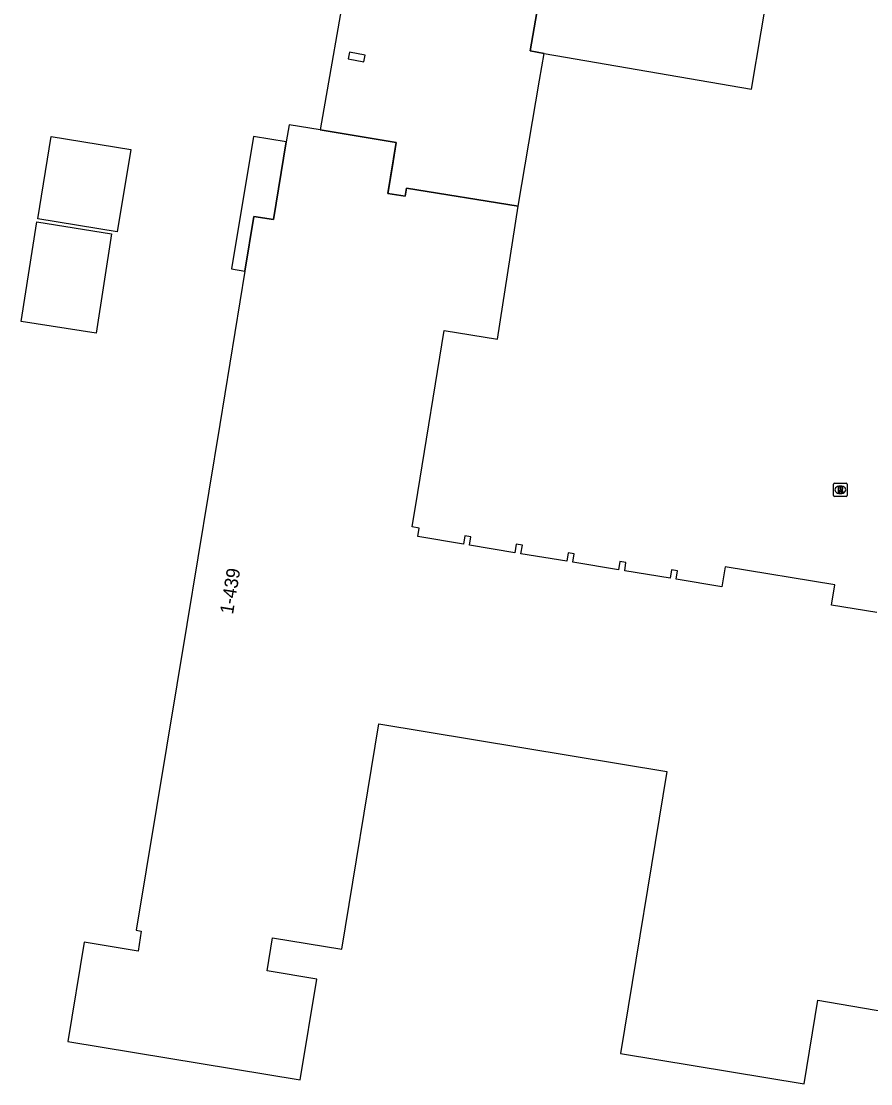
# Model space of a CAD drawing. Extents: x 161258 to 161838, y 380836 to 381727.
# Drawn here: x 161593.1 to 161656.3, y 380892.6 to 380971.7 of the extents above; entities that cross this region are included whole.
import ezdxf

# ---------------------------------------------------------------- set-up
doc = ezdxf.new("R2010")
doc.units = 0
for name, color, linetype in [('IMGEO_Pand', 7, 'Continuous'), ('IMGEO_Pand_nummerreeks', 7, 'Continuous'), ('IMGEO_Pand_overbouw', 7, 'Continuous'), ('IMGEO_Rioolput', 7, 'Continuous')]:
    doc.layers.add(name, color=color, linetype=linetype)

msp = doc.modelspace()

# ---------------------------------------------------------------- linework, layer by layer
at = {"layer": 'IMGEO_Pand'}
for points in [[(161632.262, 380976.901), (161630.974, 380969.465), (161632.027, 380969.284), (161647.439, 380966.629), (161648.17, 380970.892), (161648.549, 380973.103), (161651.15, 380972.652), (161651.976, 380977.422), (161651.777, 380977.456), (161649.385, 380977.871), (161654.985, 381010.445), (161638.525, 381013.267), (161638.42, 381012.654), (161638.251, 381011.67), (161631.061, 381012.91), (161630.098, 381007.334), (161629.73, 381005.204), (161629.086, 381001.476), (161636.289, 381000.232), (161632.862, 380980.375)], [(161618.593, 380968.659), (161618.689, 380969.154), (161617.523, 380969.382), (161617.426, 380968.888), (161618.593, 380968.659)], [(161656.763, 380927.677), (161653.392, 380928.226), (161653.642, 380929.725), (161645.499, 380931.083), (161645.249, 380929.584), (161641.842, 380930.147), (161641.949, 380930.781), (161641.499, 380930.857), (161641.392, 380930.221), (161638.012, 380930.779), (161638.107, 380931.409), (161637.65, 380931.478), (161637.556, 380930.855), (161634.158, 380931.416), (161634.257, 380932.051), (161633.801, 380932.122), (161633.703, 380931.491), (161630.295, 380932.054), (161630.398, 380932.688), (161629.943, 380932.762), (161629.84, 380932.129), (161626.462, 380932.687), (161626.562, 380933.32), (161626.107, 380933.392), (161626.007, 380932.763), (161622.613, 380933.323), (161622.717, 380933.965), (161622.19, 380934.05), (161622.609, 380936.618), (161624.576, 380948.664), (161628.543, 380948.011), (161630.074, 380957.903), (161621.778, 380959.252), (161621.681, 380958.659), (161620.398, 380958.868), (161621.003, 380962.649), (161615.362, 380963.591), (161613.042, 380963.978), (161612.832, 380962.698), (161611.885, 380956.915), (161610.425, 380957.156), (161609.753, 380953.08), (161607.873, 380941.675), (161605.418, 380926.784), (161601.667, 380904.031), (161602.032, 380903.971), (161601.805, 380902.485), (161597.789, 380903.145), (161596.574, 380895.756), (161613.874, 380892.912), (161613.898, 380893.058), (161615.108, 380900.4), (161611.397, 380901.012), (161611.802, 380903.469), (161616.963, 380902.618), (161619.727, 380919.386), (161641.159, 380915.853), (161637.699, 380894.863), (161651.365, 380892.611), (161652.39, 380898.827), (161667.853, 380896.175)], [(161594.332, 380956.975), (161595.338, 380963.099), (161601.251, 380962.127), (161600.245, 380956.004), (161594.332, 380956.975)], [(161599.831, 380955.864), (161598.67, 380948.457), (161593.107, 380949.329), (161594.268, 380956.736), (161599.831, 380955.864)]]:
    msp.add_lwpolyline(points, dxfattribs=at)
at = {"layer": 'IMGEO_Pand_overbouw'}
msp.add_lwpolyline([(161617.447, 380975.661), (161615.362, 380963.591), (161621.003, 380962.649), (161620.701, 380960.759), (161620.398, 380958.868), (161621.681, 380958.659), (161621.778, 380959.252), (161630.074, 380957.903), (161631.682, 380967.278), (161632.027, 380969.284), (161630.974, 380969.465), (161632.262, 380976.901)], dxfattribs=at)
msp.add_lwpolyline([(161609.753, 380953.08), (161610.425, 380957.156), (161611.885, 380956.915), (161612.832, 380962.698), (161610.4, 380963.103), (161608.758, 380953.246)], close=True, dxfattribs=at)
at = {"layer": 'IMGEO_Rioolput'}
for p, q in [((161653.556, 380936.384), (161653.556, 380937.236)), ((161653.631, 380937.31), (161654.483, 380937.31)), ((161654.044, 380937.09), (161654.069, 380937.09)), ((161654.557, 380937.236), (161654.557, 380936.384)), ((161654.483, 380936.31), (161653.631, 380936.31)), ((161654.067, 380936.53), (161654.042, 380936.53))]:
    msp.add_line(p, q, dxfattribs=at)
for points in [[(161653.556, 380936.384), (161653.556, 380937.236)], [(161653.631, 380937.31), (161654.483, 380937.31)], [(161654.145, 380937.008), (161653.893, 380937.01), (161653.893, 380936.61)], [(161653.893, 380936.61), (161654.017, 380936.61), (161654.017, 380936.772), (161654.028, 380936.772)], [(161654.071, 380936.929), (161654.017, 380936.929), (161654.017, 380936.848)], [(161654.017, 380936.848), (161654.069, 380936.848)], [(161654.075, 380936.743), (161654.146, 380936.61), (161654.286, 380936.61), (161654.221, 380936.736)], [(161654.557, 380937.236), (161654.557, 380936.384)], [(161654.483, 380936.31), (161653.631, 380936.31)]]:
    msp.add_lwpolyline(points, dxfattribs=at)
for centre, radius, start, end in [((161653.633, 380937.234), 0.0765, 91.55205, 178.44795), ((161653.633, 380937.234), 0.0765, 91.55205, 178.44795), ((161654.027, 380936.719), 0.0533, 26.02933, 88.69889), ((161654.053, 380937.037), 0.19, 274.7715, 282.96867), ((161654.077, 380936.833), 0.0964, 77.00612, 93.18647), ((161654.091, 380936.89), 0.0378, 276.66336, 79.67722), ((161654.144, 380936.898), 0.109, 350.36119, 89.41601), ((161654.142, 380936.898), 0.112, 277.58423, 350.98172), ((161654.126, 380936.683), 0.108, 29.51342, 73.79051), ((161654.481, 380937.234), 0.0765, 1.55205, 88.44795), ((161654.481, 380937.234), 0.0765, 1.55205, 88.44795), ((161653.633, 380936.386), 0.0765, 181.55205, 268.44795), ((161653.633, 380936.386), 0.0765, 181.55205, 268.44795), ((161654.481, 380936.386), 0.0765, 271.55205, 358.44795), ((161654.481, 380936.386), 0.0765, 271.55205, 358.44795)]:
    msp.add_arc(centre, radius, start, end, dxfattribs=at)
for centre, major_axis, ratio, start_param, end_param in [((161654.043, 380936.81), (-0.387, 0.002), 0.722429, 4.712389, 7.853982), ((161654.068, 380936.81), (-0.39, 0.002), 0.717154, 1.570796, 4.712389)]:
    msp.add_ellipse(centre, major_axis=major_axis, ratio=ratio, start_param=start_param, end_param=end_param, dxfattribs=at)

# ---------------------------------------------------------------- texts
at = {"layer": 'IMGEO_Pand_nummerreeks'}
msp.add_text('1-439', height=1, rotation=80.63885, dxfattribs=at).set_placement((161608.862, 380927.509))

doc.saveas('drawing.dxf')
